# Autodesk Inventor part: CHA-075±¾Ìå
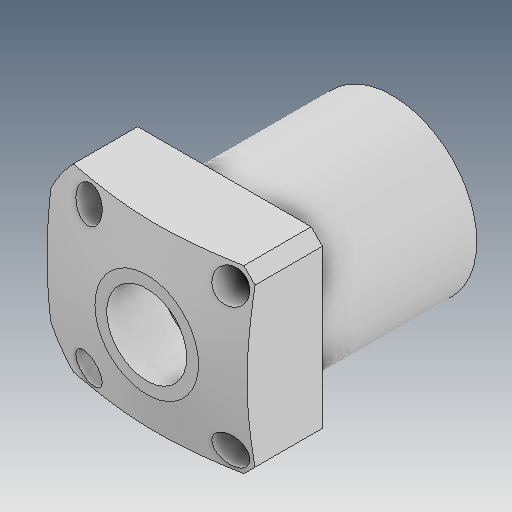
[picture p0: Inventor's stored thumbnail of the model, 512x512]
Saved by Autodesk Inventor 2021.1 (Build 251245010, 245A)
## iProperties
Created: 2019-05
Part Number: CHA-075±¾Ìå
Material: Ogólny
Document SubType Name: Modeling
Designer: user
Density: 1 g/cm^3
Appearance: Domyślna
Author: user
Revision Number: ÈÎºÎ
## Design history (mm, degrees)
feature "ÊäÈë1"
node "Bryła1"
